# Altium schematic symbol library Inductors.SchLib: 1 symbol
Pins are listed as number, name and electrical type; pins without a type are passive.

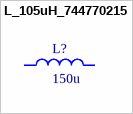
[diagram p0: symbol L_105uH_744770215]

## L_105uH_744770215
designator L?, comment 150u
Power Inductor (SMD), 150 µH, 1.8 A, Shielded, 1.8 A, WE-PD, 12mm x 12mm x 8mm; Manufacturer: Wurth Elektronik; Mfr Part Num.: 744770215; RMS Current: 1.8A; DC Resistance Max: 0.28R
footprint 744770215
footprint 744770215
pins: 1 Pin 1, 2 Pin 2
